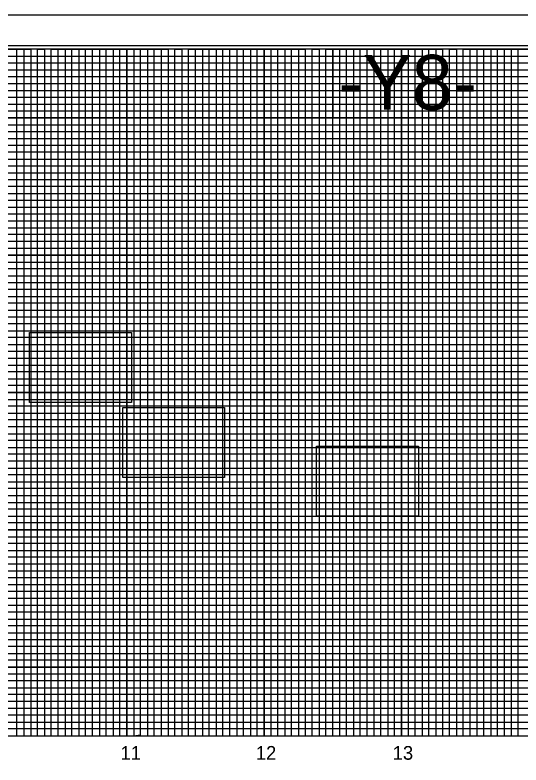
# Model space of a CAD drawing. Extents: x 1779926 to 1781626, y 618464 to 619564.
# Drawn here: x 1780862 to 1781230, y 619018 to 619564 of the extents above; entities that cross this region are included whole.
import ezdxf

# ---------------------------------------------------------------- set-up
doc = ezdxf.new("R2010")
doc.units = 0
for name, color, linetype in [('Exist Vertical Profile Horizontal Axis Label Major', 7, 'Continuous'), ('Prop DSN Text', 7, 'Continuous'), ('Prop Grid Mask', 7, 'Continuous'), ('Sheet DOT Grid CELL', 7, 'Continuous'), ('Sheet Layout Profile Border Port 1', 7, 'Continuous'), ('Sheet Plot Border Inside CELL', 7, 'Continuous'), ('Sheet Plot Border Outside CELL', 7, 'Continuous'), ('Sheet Profile CELL', 7, 'Continuous'), ('Sheet Profile Grid Major CELL', 7, 'Continuous'), ('Sheet Profile Grid Middle CELL', 7, 'Continuous'), ('Sheet Profile Grid Minor CELL', 7, 'Continuous')]:
    doc.layers.add(name, color=color, linetype=linetype)

msp = doc.modelspace()

# ---------------------------------------------------------------- linework, layer by layer
at = {"layer": 'Prop Grid Mask'}
for points in [[(1781217.98, 619539.19), (1781092.96, 619539.19), (1781092.96, 619489.19), (1781217.98, 619489.19)], [(1780872.14, 619332.9), (1780946.39, 619332.9), (1780946.39, 619281.99), (1780872.14, 619281.99)], [(1780939.96, 619278.31), (1781014.21, 619278.31), (1781014.21, 619227.41), (1780939.96, 619227.41)], [(1781081.21, 619250.07), (1781155.46, 619250.07), (1781155.46, 619199.16), (1781081.21, 619199.16)]]:
    msp.add_lwpolyline(points, close=True, dxfattribs=at)
at = {"layer": 'Sheet DOT Grid CELL'}
for p, q in [((1780892.96, 619039.19), (1780892.96, 619539.19)), ((1780942.96, 619039.19), (1780942.96, 619539.19)), ((1780992.96, 619039.19), (1780992.96, 619539.19)), ((1781042.96, 619039.19), (1781042.96, 619539.19)), ((1781092.96, 619039.19), (1781092.96, 619539.19)), ((1781142.96, 619039.19), (1781142.96, 619539.19)), ((1781192.96, 619039.19), (1781192.96, 619539.19)), ((1781392.91, 619489.19), (1780092.96, 619489.19)), ((1781392.91, 619439.19), (1780092.96, 619439.19)), ((1781392.96, 619389.19), (1780092.96, 619389.19)), ((1781392.91, 619339.19), (1780092.96, 619339.19)), ((1781592.96, 619289.19), (1780092.96, 619289.19)), ((1781592.96, 619239.19), (1780092.96, 619239.19)), ((1781592.96, 619189.19), (1780092.96, 619189.19)), ((1781592.96, 619139.19), (1780092.96, 619139.19)), ((1781592.96, 619089.19), (1780092.96, 619089.19))]:
    msp.add_line(p, q, dxfattribs=at)
at = {"layer": 'Sheet Layout Profile Border Port 1'}
for points in [[(1781542.96, 619099.19), (1781542.96, 619314.19), (1781392.91, 619314.19), (1781392.96, 619539.19), (1780142.96, 619539.19), (1780142.96, 619039.19), (1781542.96, 619039.19), (1781542.96, 619049.19)], [(1780142.96, 619378.14), (1780142.96, 619039.19), (1781542.96, 619039.19), (1781542.96, 619314.19)]]:
    msp.add_lwpolyline(points, dxfattribs=at)
at = {"layer": 'Sheet Plot Border Inside CELL'}
msp.add_lwpolyline([(1779938.96, 618486.64), (1781605.46, 618486.64), (1781605.46, 619541.74), (1779938.96, 619541.74)], close=True, dxfattribs=at)
at = {"layer": 'Sheet Plot Border Outside CELL'}
msp.add_lwpolyline([(1779925.96, 618464.19), (1781625.96, 618464.19), (1781625.96, 619564.19), (1779925.96, 619564.19)], close=True, dxfattribs=at)
at = {"layer": 'Sheet Profile CELL'}
msp.add_line((1780092.96, 619039.19), (1781592.96, 619039.19), dxfattribs=at)
msp.add_lwpolyline([(1781592.96, 619539.19), (1780092.96, 619539.19), (1780092.96, 618489.19), (1781592.96, 618489.19)], close=True, dxfattribs=at)
at = {"layer": 'Sheet Profile Grid Major CELL'}
for points in [[(1780842.96, 619039.19), (1780892.96, 619039.19), (1780892.96, 619539.19), (1780942.96, 619539.19), (1780942.96, 619039.19), (1780992.96, 619039.19), (1780992.96, 619539.19), (1781042.96, 619539.19), (1781042.96, 619039.19), (1781092.96, 619039.19), (1781092.96, 619539.19), (1781142.96, 619539.19), (1781142.96, 619039.19), (1781192.96, 619039.19), (1781192.96, 619539.19), (1781242.96, 619539.19), (1781242.96, 619039.19), (1781292.96, 619039.19), (1781292.96, 619539.19), (1781342.96, 619539.19), (1781342.96, 619039.19), (1781392.96, 619039.19), (1781392.96, 619539.19), (1781419.26, 619539.19)], [(1780092.96, 619489.19), (1781392.96, 619489.19)], [(1781392.96, 619439.19), (1780092.96, 619439.19), (1780092.96, 619389.19), (1781392.96, 619389.19)], [(1781392.96, 619339.19), (1780092.96, 619339.19), (1780092.96, 619289.19), (1781592.96, 619289.19)], [(1781592.96, 619239.19), (1780092.96, 619239.19), (1780092.96, 619189.19), (1781592.96, 619189.19)], [(1781592.96, 619139.19), (1780092.96, 619139.19), (1780092.96, 619139.19), (1780092.96, 619089.19), (1781592.96, 619089.19)]]:
    msp.add_lwpolyline(points, dxfattribs=at)
at = {"layer": 'Sheet Profile Grid Middle CELL'}
msp.add_line((1780092.96, 619514.19), (1781392.91, 619514.19), dxfattribs=at)
for points in [[(1780817.96, 619539.19), (1780867.96, 619539.19), (1780867.96, 619039.19), (1780917.96, 619039.19), (1780917.96, 619539.19), (1780967.96, 619539.19), (1780967.96, 619039.19), (1781017.96, 619039.19), (1781017.96, 619539.19), (1781067.96, 619539.19), (1781067.96, 619039.19), (1781117.96, 619039.19), (1781117.96, 619539.19), (1781167.96, 619539.19), (1781167.96, 619039.19), (1781217.96, 619039.19), (1781217.96, 619539.19), (1781267.96, 619539.19)], [(1781392.96, 619464.19), (1780092.96, 619464.19), (1780092.96, 619414.19), (1781392.96, 619414.19)], [(1781392.91, 619364.19), (1780092.96, 619364.19), (1780092.96, 619314.19), (1781417.96, 619314.19)], [(1781592.96, 619264.19), (1780092.96, 619264.19), (1780092.96, 619214.19), (1781592.96, 619214.19)], [(1781592.96, 619164.19), (1780092.96, 619164.19), (1780092.96, 619114.19), (1781592.96, 619114.19)], [(1781592.96, 619064.19), (1780092.96, 619064.19)]]:
    msp.add_lwpolyline(points, dxfattribs=at)
at = {"layer": 'Sheet Profile Grid Minor CELL'}
for p, q in [((1780142.96, 619534.19), (1781392.96, 619534.19)), ((1781392.96, 619529.19), (1780142.96, 619528.84)), ((1780142.96, 619524.19), (1781392.96, 619524.19)), ((1781392.91, 619404.19), (1780142.96, 619404.19)), ((1781392.96, 619399.19), (1780142.96, 619399.19)), ((1781392.96, 619394.19), (1780142.96, 619394.19)), ((1780142.96, 619384.19), (1781392.96, 619384.19)), ((1781392.96, 619379.19), (1780142.96, 619379.19)), ((1780142.96, 619374.19), (1781392.91, 619374.19)), ((1781392.91, 619354.19), (1780142.96, 619354.19)), ((1780142.96, 619349.19), (1781392.91, 619349.19)), ((1781392.91, 619329.19), (1780142.96, 619329.19)), ((1780142.96, 619324.19), (1781392.91, 619324.19)), ((1781542.96, 619304.19), (1780142.96, 619304.19)), ((1780142.96, 619299.19), (1781542.96, 619299.19)), ((1781542.96, 619294.19), (1780142.96, 619294.19)), ((1780142.96, 619284.19), (1781542.96, 619284.19)), ((1781542.96, 619279.19), (1780142.96, 619279.19)), ((1780142.96, 619274.19), (1781542.96, 619274.19)), ((1781542.96, 619269.19), (1780142.96, 619269.19)), ((1780142.96, 619259.19), (1781542.96, 619259.19)), ((1781542.96, 619254.19), (1780142.96, 619254.19)), ((1780142.96, 619249.19), (1781542.96, 619249.19)), ((1781542.96, 619244.19), (1780142.96, 619244.19)), ((1780142.96, 619234.19), (1781542.96, 619234.19)), ((1781542.96, 619229.19), (1780142.96, 619229.19)), ((1780142.96, 619224.19), (1781542.96, 619224.19)), ((1781542.96, 619219.19), (1780142.96, 619219.19)), ((1780142.96, 619209.19), (1781542.96, 619209.19)), ((1781542.96, 619204.19), (1780142.96, 619204.19)), ((1780142.96, 619199.19), (1781542.96, 619199.19)), ((1781542.96, 619194.19), (1780142.96, 619194.19)), ((1780142.96, 619184.19), (1781542.96, 619184.19)), ((1781542.96, 619179.19), (1780142.96, 619179.19)), ((1780142.96, 619174.19), (1781542.96, 619174.19)), ((1781542.96, 619169.19), (1780142.96, 619169.19)), ((1780142.96, 619159.19), (1781542.96, 619159.19)), ((1781542.96, 619154.19), (1780142.96, 619154.19)), ((1781542.96, 619149.19), (1780142.96, 619149.19)), ((1781542.96, 619144.19), (1780142.96, 619144.19)), ((1780142.96, 619134.19), (1781542.96, 619134.19)), ((1781542.96, 619129.19), (1780142.96, 619129.19)), ((1780142.96, 619124.19), (1781542.96, 619124.19)), ((1781542.96, 619119.19), (1780142.96, 619119.19)), ((1780142.96, 619109.19), (1781542.96, 619109.19)), ((1781542.96, 619104.19), (1780142.96, 619104.19)), ((1780142.96, 619099.19), (1781542.96, 619099.19)), ((1781542.96, 619094.19), (1780142.96, 619094.19)), ((1780142.96, 619084.19), (1781542.96, 619084.19)), ((1781542.96, 619079.19), (1780142.96, 619079.19)), ((1780142.96, 619074.19), (1781542.96, 619074.19)), ((1781542.96, 619069.19), (1780142.96, 619069.19)), ((1780142.96, 619059.19), (1781542.96, 619059.19)), ((1781542.96, 619054.19), (1780142.96, 619054.19)), ((1780142.96, 619049.19), (1781542.96, 619049.19))]:
    msp.add_line(p, q, dxfattribs=at)
for points in [[(1780857.96, 619039.19), (1780862.96, 619039.19), (1780862.96, 619539.19), (1780872.96, 619539.19), (1780872.96, 619039.19), (1780877.96, 619039.19), (1780877.96, 619539.19), (1780882.96, 619539.19), (1780882.96, 619039.19), (1780887.96, 619039.19), (1780887.96, 619539.19), (1780897.96, 619539.19), (1780897.96, 619039.19), (1780902.96, 619039.19), (1780902.96, 619539.19), (1780907.96, 619539.19), (1780907.96, 619039.19), (1780912.96, 619039.19), (1780912.96, 619539.19), (1780922.96, 619539.19), (1780922.96, 619039.19), (1780927.96, 619039.19), (1780927.96, 619539.19), (1780932.96, 619539.19), (1780932.96, 619039.19), (1780937.96, 619039.19), (1780937.96, 619539.19), (1780947.96, 619539.19), (1780947.96, 619039.19), (1780952.66, 619039.74), (1780952.96, 619039.19), (1780952.96, 619539.19), (1780957.96, 619539.19), (1780957.96, 619039.19), (1780962.96, 619039.19), (1780962.96, 619539.19), (1780972.96, 619539.19), (1780972.96, 619039.19), (1780977.96, 619039.19)], [(1780977.96, 619039.19), (1780977.96, 619539.19), (1780982.96, 619539.19), (1780982.96, 619039.19), (1780987.96, 619039.19), (1780987.96, 619539.19), (1780997.96, 619539.19), (1780997.96, 619039.19), (1781002.96, 619039.19), (1781002.96, 619539.19), (1781007.96, 619539.19), (1781007.96, 619039.19), (1781012.96, 619039.19), (1781012.96, 619539.19), (1781022.96, 619539.19), (1781022.96, 619039.19), (1781027.96, 619039.19), (1781027.96, 619539.19), (1781032.96, 619539.19), (1781032.96, 619039.19), (1781037.96, 619039.19), (1781037.96, 619539.19), (1781047.96, 619539.19), (1781047.96, 619039.19), (1781052.96, 619039.19), (1781052.96, 619539.19), (1781057.96, 619539.19), (1781057.96, 619039.19), (1781062.96, 619039.19), (1781062.96, 619539.19), (1781072.96, 619539.19), (1781072.96, 619039.19), (1781077.96, 619039.19), (1781077.96, 619539.19), (1781082.96, 619539.19), (1781082.96, 619039.19), (1781087.96, 619039.19), (1781087.96, 619539.19), (1781097.96, 619539.19), (1781097.96, 619039.19), (1781102.96, 619039.19), (1781102.96, 619539.19), (1781107.96, 619539.19), (1781107.96, 619039.19), (1781112.96, 619039.19), (1781112.96, 619539.19), (1781122.96, 619539.19), (1781122.96, 619039.19), (1781127.96, 619039.19), (1781127.96, 619539.19), (1781132.96, 619539.19), (1781132.96, 619039.19), (1781137.96, 619039.19), (1781137.96, 619539.19), (1781147.96, 619539.19), (1781147.96, 619039.19), (1781152.96, 619039.19), (1781152.96, 619539.19), (1781157.96, 619539.19), (1781157.96, 619039.19), (1781162.96, 619039.19), (1781162.96, 619539.19), (1781172.96, 619539.19), (1781172.96, 619039.19), (1781177.96, 619039.19), (1781177.96, 619539.19), (1781182.96, 619539.19), (1781182.96, 619039.19), (1781187.96, 619039.19), (1781187.96, 619539.19), (1781197.96, 619539.19), (1781197.96, 619039.19), (1781202.96, 619039.19), (1781202.96, 619539.19), (1781207.96, 619539.19), (1781207.96, 619039.19), (1781212.96, 619039.19), (1781212.96, 619539.19), (1781222.96, 619539.19), (1781222.96, 619039.19), (1781227.96, 619039.19), (1781227.96, 619539.19), (1781232.96, 619539.19)], [(1781392.96, 619519.19), (1780142.96, 619519.19), (1780142.96, 619509.19), (1781392.96, 619509.19)], [(1781392.91, 619504.19), (1780142.96, 619504.19), (1780142.96, 619499.19), (1781392.96, 619499.19)], [(1781392.96, 619494.19), (1780142.96, 619494.19), (1780142.96, 619484.19), (1781392.96, 619484.19)], [(1781392.96, 619479.19), (1780142.96, 619479.19), (1780142.96, 619474.19), (1781392.96, 619474.19)], [(1781392.96, 619469.19), (1780142.96, 619469.19), (1780142.96, 619459.19), (1781392.96, 619459.19)], [(1781392.96, 619454.19), (1780142.96, 619454.19), (1780142.96, 619449.19), (1781392.96, 619449.19)], [(1781392.96, 619444.19), (1780142.96, 619444.19), (1780142.96, 619434.19), (1781392.96, 619434.19)], [(1781392.96, 619429.09), (1780143.06, 619429.09), (1780143.06, 619424.19), (1781392.96, 619424.19)], [(1781392.96, 619419.19), (1780142.96, 619419.19), (1780142.96, 619409.19), (1781392.96, 619409.19)], [(1781392.91, 619369.19), (1780142.96, 619369.19), (1780142.96, 619359.19), (1781392.91, 619359.19)], [(1781392.91, 619344.19), (1780142.96, 619344.19), (1780142.96, 619334.19), (1781392.91, 619334.19)], [(1781392.91, 619319.19), (1780142.96, 619319.19), (1780142.96, 619309.19), (1781542.96, 619309.19)], [(1781542.96, 619044.19), (1780142.96, 619044.19)]]:
    msp.add_lwpolyline(points, dxfattribs=at)

# ---------------------------------------------------------------- texts
at = {"layer": 'Exist Vertical Profile Horizontal Axis Label Major'}
for s, p in [('11', (1780938.38, 619021.69)), ('12', (1781036.93, 619021.69)), ('13', (1781136.61, 619021.69))]:
    msp.add_text(s, height=10, dxfattribs=at).set_placement(p)
at = {"layer": 'Prop DSN Text'}
msp.add_text('-Y8-', height=40, dxfattribs=at).set_placement((1781097.01, 619495.14))

doc.saveas('drawing.dxf')
